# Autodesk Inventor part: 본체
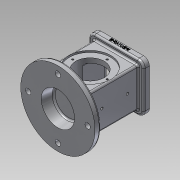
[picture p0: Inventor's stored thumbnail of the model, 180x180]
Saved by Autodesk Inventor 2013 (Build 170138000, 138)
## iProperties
Created: 2018-10
Part Number: 본체
Material: 알루미늄 6061
Document SubType Name: Modeling
Designer: hana-cad17
Density: 2.71 g/cm^3
Mass: 988.222 g
Surface Area: 743.902 cm^2
Volume: 364.657 cm^3
Author: hana-cad17
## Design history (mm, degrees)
sketch "스케치1"
  geometry: C1 r 62.5 at (0, 0); 1 further point
  constraints: 1 centre point, 1 coincident
  dimensions: "d0" = 125 diameter of C1
extrude "돌출1" new body sketch "스케치1" distance "d1" = 10; taper "d2" = 0 deg
sketch "스케치2"
  geometry: L1 (37, 33)-(-37, 33); L2 (-37, 33)-(-37, -33); L3 (-37, -33)-(37, -33); L4 (37, -33)-(37, 33); L5 (37, 33)-(-37, -33); L6 (-37, 33)-(37, -33); C1 r 62.5 at (0, 0) reference
  constraints: 12 end point, 2 midpoint, 2 parallel, 1 horizontal, 1 perpendicular
  dimensions: "d5" = 66 distance of L3.end L1.start; "d6" = 74 distance of L1.start L1.end
extrude "돌출2" join sketch "스케치2" distance "d7" = 88; taper "d8" = 0 deg
sketch "스케치3"
  geometry: L1 (-46, 41)-(46, 41); L2 (46, 41)-(46, -41); L3 (46, -41)-(-46, -41); L4 (-46, -41)-(-46, 41); L5 (-46, 41)-(46, -41); L6 (46, 41)-(-46, -41); 1 further point
  constraints: 12 end point, 2 midpoint, 2 parallel, 1 horizontal, 1 perpendicular
  dimensions: "d9" = 92 distance of L2.end L3.end; "d10" = 82 distance of L1.end L2.end
extrude "돌출3" join sketch "스케치3" distance "d11" = 10; taper "d12" = 0 deg
sketch "스케치4"
  geometry: L1 (-25.5, -10)-(99.5, -10) reference; C1 r 35 at (37, 44); 1 further point
  constraints: 1 centre point, 1 vertical alignment
  dimensions: "d13" = 70 diameter of C1; "d14" = 54 distance from line of L1 C1.centre
extrude "돌출4" cut sketch "스케치4" distance "d15" = 3; taper "d16" = 0 deg
sketch "스케치5"
  geometry: C1 r 35 at (0, 0) reference; C2 r 24 at (0, 0); 1 further point
  constraints: 1 centre point, 1 coincident
  dimensions: "d17" = 48 diameter of C2
extrude "돌출5" cut sketch "스케치5" stored distance "d18" = 3; taper "d19" = 0 deg
sketch "스케치6" dims "d20" = 58
  geometry: C1 r 24 at (0, 0) reference; C2 r 35 at (0, 0) reference; 3 further points
  constraints: 2 vertical alignment, 1 coincident, 2 other
hole "구멍1" sketch "스케치6" at (0, 29) diameter "d21" = 3.242; stored, may be unused: countersink angle "d25" = 90 deg, drill point angle "d27" = 118 deg; dims "d22" = 4, "d23" = 4, "d24" = 2, "d26" = 6
sketch "스케치7"
  geometry: L1 (-26, 26)-(26, 26); L2 (26, 26)-(26, -26); L3 (26, -26)-(-26, -26); L4 (-26, -26)-(-26, 26); L5 (-26, 26)-(26, -26); L6 (26, 26)-(-26, -26); 1 further point
  constraints: 12 end point, 2 midpoint, 2 parallel, 1 horizontal, 1 perpendicular
  dimensions: "d31" = 52 distance of L2.end L3.end; "d32" = 52 distance of L1.end L2.end
extrude "돌출6" cut sketch "스케치7" distance "d33" = 8; taper "d34" = 0 deg
sketch "스케치8"
  geometry: L1 (-22, 22)-(22, 22); L2 (22, 22)-(22, -22); L3 (22, -22)-(-22, -22); L4 (-22, -22)-(-22, 22); L5 (-22, 22)-(22, -22); L6 (22, 22)-(-22, -22); 1 further point
  constraints: 12 end point, 2 midpoint, 2 parallel, 1 horizontal, 1 perpendicular
  dimensions: "d35" = 44 distance of L2.end L3.end; "d36" = 44 distance of L1.end L2.end
extrude "돌출7" cut sketch "스케치8" distance "d37" = 74; taper "d38" = 0 deg
sketch "스케치9"
  geometry: C1 r 62.5 at (0, 0) reference; C2 r 28 at (0, 0)
  constraints: 1 centre point, 1 coincident
  dimensions: "d39" = 56 diameter of C2
extrude "돌출8" cut sketch "스케치9" distance "d40" = 18; taper "d41" = 0 deg
feature "면 기울기1" dims angle "d42" = 10 deg
sketch "스케치10" dims "d43" = 100
  geometry: C1 r 62.5 at (0, 0) reference; C2 r 4.5 at (0, 50); 2 further points
  constraints: 2 coincident, 2 vertical alignment, 1 centre point, 2 other
  dimensions: "d44" = 9 diameter of C2
extrude "돌출9" cut sketch "스케치10" stored distance "d45" = 18; taper "d46" = 0 deg
fillet "모깎기1" dims "d50" = 10
sketch "스케치11"
  geometry: A1 r 10 centre (36, -31) between (36, -41) and (46, -31) reference; A2 r 10 centre (36, 31) between (46, 31) and (36, 41) reference; A3 r 10 centre (-36, 31) between (-36, 41) and (-46, 31) reference; A4 r 10 centre (-36, -31) between (-46, -31) and (-36, -41) reference; 5 further points
  constraints: 4 coincident
hole "구멍2" sketch "스케치11" at (-36, 31), (36, 31), (36, -31), (-36, -31) diameter "d51" = 3.242; stored, may be unused: countersink angle "d55" = 90 deg, drill point angle "d57" = 118 deg; dims "d52" = 4, "d53" = 4, "d54" = 2, "d56" = 6
node "작업 평면1"
sketch "스케치12"
  geometry: L1 (-46, 108)-(-46, 98) reference; L2 (-36, 108)-(36, 108) reference; 2 further points
  constraints: 1 other
  dimensions: "d59" = 46 distance from line of point (0, 104) L1; "d60" = 4 distance from line of point (0, 104) L2
feature "엠보싱1" sketch "스케치12" dims "d61" = 0.5, "d62" = 0
fillet "모깎기2" dims "d63" = 3
fillet "모깎기3" dims "d64" = 3
fillet "모깎기4" dims "d65" = 3
fillet "모깎기5" dims "d66" = 3
fillet "모깎기6" dims "d67" = 3
fillet "모깎기7" dims "d68" = 3
fillet "모깎기8" dims "d69" = 3
fillet "모깎기9" dims "d70" = 3
fillet "모깎기10" dims "d71" = 3
fillet "모깎기11" dims "d72" = 3
chamfer "모따기1" distance "d73" = 1; stored, may be unused: second distance "d74" = 2, angle "d75" = 45 deg
sketch "스케치13"
  geometry: L1 (-32.5, -13)-(92.5, -13) reference; 4 further points
  constraints: 2 vertical alignment, 1 midpoint
  dimensions: "d76" = 37 distance from line of point (30, 24) L1; "d77" = 43 distance of point (30, 67) point (30, 24)
hole "구멍3" sketch "스케치13" at (30, 24), (30, 67) diameter "d78" = 4.134; stored, may be unused: countersink angle "d82" = 90 deg, drill point angle "d84" = 118 deg; dims "d79" = 15, "d80" = 4, "d81" = 2, "d83" = 15
node "솔리드1"
pattern_circular "원형 패턴1" dims angle "d29" = 360 deg
mirror "대칭1"
pattern_circular "원형 패턴2" dims angle "d48" = 360 deg
other parameters: "d58" = 91.25
